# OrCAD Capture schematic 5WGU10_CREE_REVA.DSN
size B
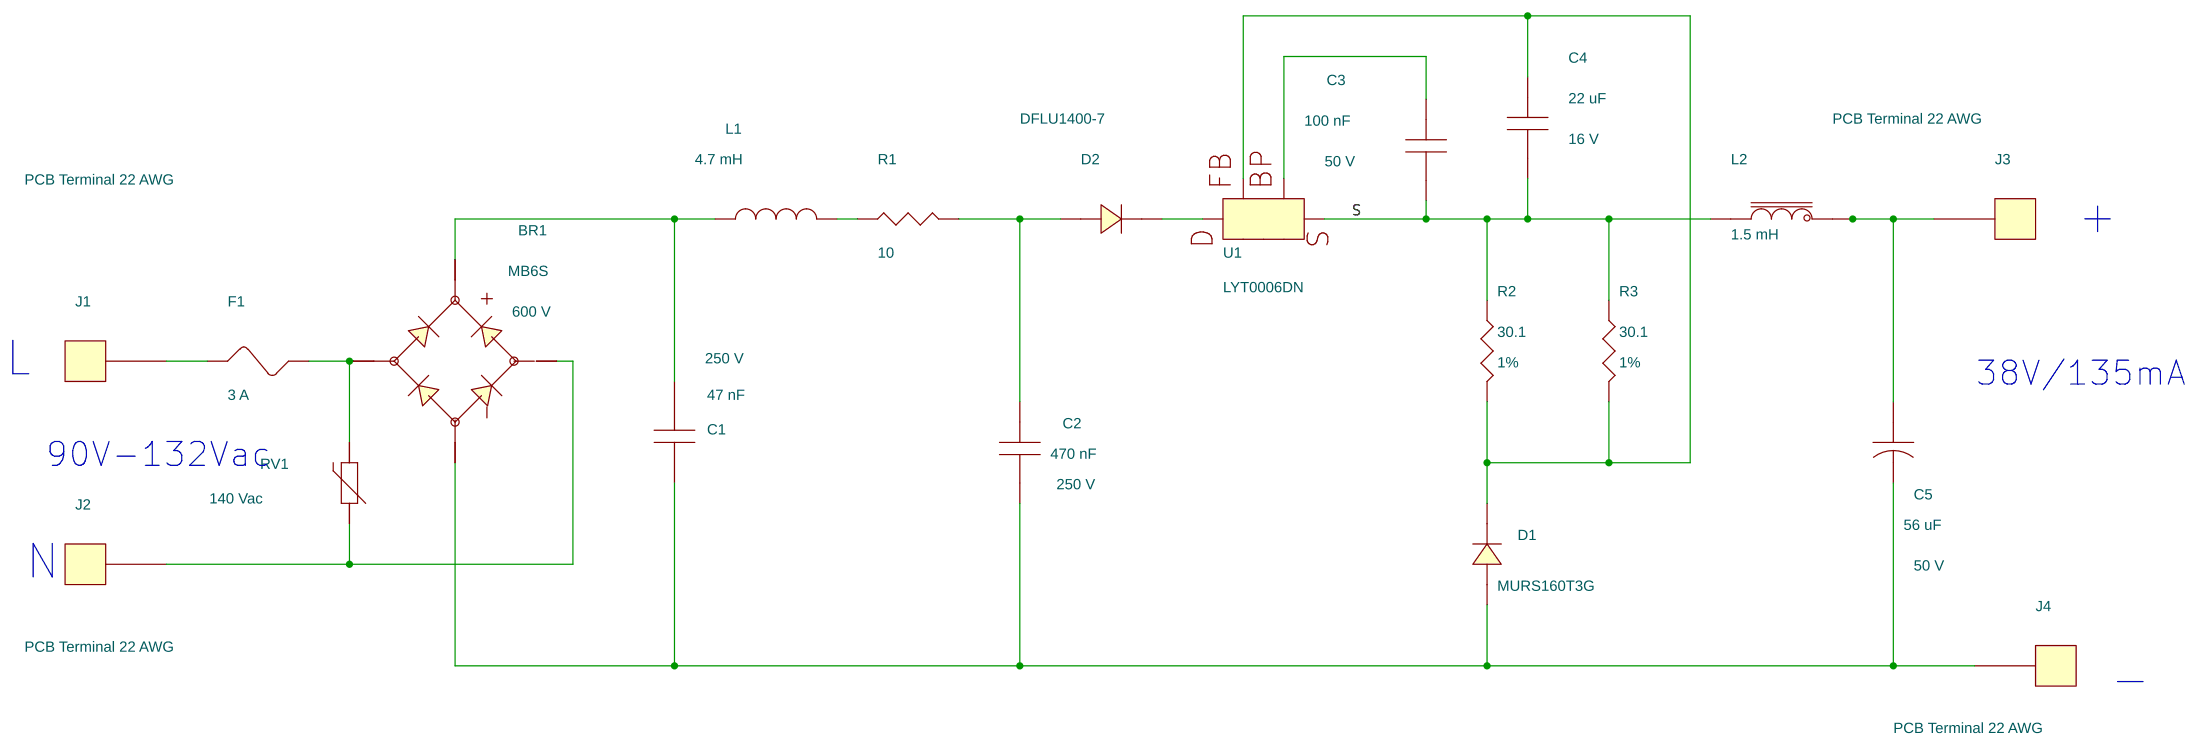
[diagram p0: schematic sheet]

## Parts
BR1  MB6S  [pismsoic4]
C1  47 nF  [pi_np_caprad315x170ls200d030]
C2  470 nF  [pinpcaprad500x240400040]
C3  100 nF  [pismc1206]
C4  22 uF  [pismc1206]
C5  56 uF  [pipolcapcyld250ls100030]
D1  MURS160T3G  [pismsmb]
D2  DFLU1400-7  [pismddflr120012]
F1  3 A  [pivaxiald100ls100030]
J1  PCB Terminal 22 AWG  [pi_hole_22awg]
J2  PCB Terminal 22 AWG  [pi_hole_22awg]
J3  PCB Terminal 22 AWG  [pi_hole_22awg]
J4  PCB Terminal 22 AWG  [pi_hole_22awg]
L1  4.7 mH  [pichoke030dials200035]
L2  1.5 mH  [pi_choke_450hx375ls197d030]
R1  10  [pismr1206]
R2  30.1  [pismr1206]
R3  30.1  [pismr1206]
RV1  140 Vac  [pinpcaprad370x156250040]
U1  LYT0006DN  [piicsmdso8]

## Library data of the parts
BR1 = DIODE_BRIDGE_~~+-_0: ALT_SYMBOLS: pi_sm_soic4_slot; Disp_Voltage: 600 V; Part Number: 15-00498-00
C1 = CAP_NP: Disp_Voltage: 250 V; Part Number: 20-01002-00; Voltage: 250 V
C2 = CAP_NP: Disp_Voltage: 250 V; Part Number: 20-08615-00; Voltage: 250 V
C3 = CAP_NP: Disp_Voltage: 50 V; Part Number: 20-00927-00; Voltage: 50 V
C4 = CAP_NP: Disp_Voltage: 16 V; Part Number: 20-01038-00; Voltage: 16 V
C5 = CAP_POL: ALT_SYMBOLS: pipolcapcyld250ls100030h; Disp_Voltage: 50 V; FPLIST: pipolcapcyld250ls100030,pipolcapcyld250ls100030h; Part Number: 20-00057-00; Voltage: 50 V
D1 = DIODE: Part Number: 15-00487-00
D2 = DIODE: Part Number: 15-00910-00
F1 = FUSE: FPLIST: pivaxiald100ls100030,piaxiald100ls500030; Part Number: 40-00015-00
J1-J4 = TERM_1PIN: Part Number: 35-00008-00
L1 = INDUCTOR: Part Number: 30-00365-00
L2 = INDUCTOR1-2: FPLIST: pi_choke_450hx375ls197d030,pi_choke_450hx375ls197d030_H; Part Number: 30-00354-00
R1 = R: Part Number: 05-05557-00
R2 R3 = R: Disp_Tol: 1%; Part Number: 05-00047-00
RV1 = VARISTOR: Part Number: 85-00001-00
U1 = LNK30X_SO8_DN_1: Part Number: 10-00752-00

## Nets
S: C3.2 C4.2 L2.2 R2.1 R3.1 U1.5(S) U1.6(S) U1.7(S) U1.8(S)
N00373: BR1.3 C1.2 L1.1
N00556: BR1.4 C1.1 C2.2 C5.2 D1.2 J4.1
N00722: BR1.2 J2.1 RV1.1
N00762: C4.1 D1.1 R2.2 R3.2 U1.2(FB)
N08431: BR1.1 F1.1 RV1.2
N09054: F1.2 J1.1
N44848: C3.1 U1.1(BP)
N45009: C2.1 D2.2 R1.2
N47034: D2.1 U1.4(D)
N50424: C5.1 J3.1 L2.1
N52058: L1.2 R1.1

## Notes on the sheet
- +
- L
- 38V/135mA
- 90V-132Vac
- N
- _
